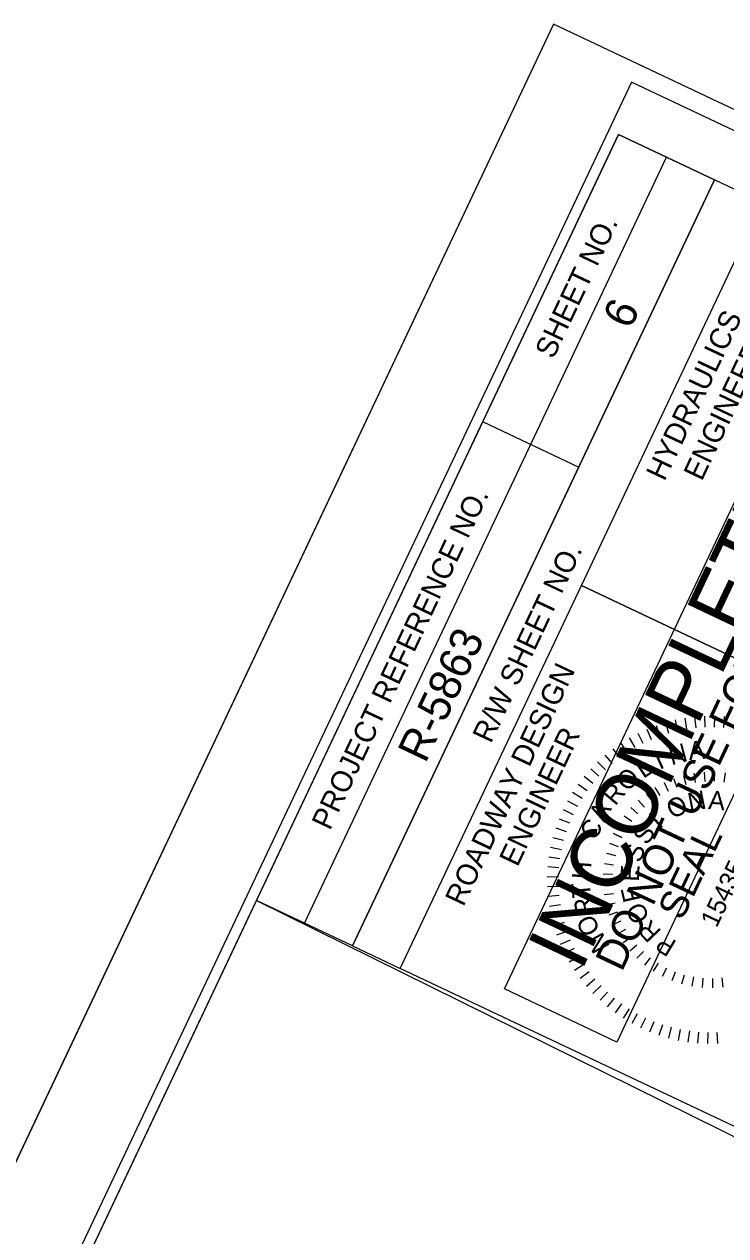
# Model space of a CAD drawing. Extents: x 555566 to 557881, y 503985 to 506091.
# Drawn here: x 556761.6 to 556927.2, y 505805.2 to 506091.2 of the extents above; entities that cross this region are included whole.
import ezdxf

# ---------------------------------------------------------------- set-up
doc = ezdxf.new("R2010")
doc.units = 0
for name, color, linetype in [('Old_Level_21', 7, 'Continuous'), ('Sheet Border Standard 30in CELL', 7, 'Continuous'), ('Sheet Clip Boundary CELL', 7, 'Continuous'), ('Sheet Cutting Line CELL', 7, 'Continuous'), ('Sheet Data Field CELL', 7, 'Continuous'), ('Sheet Plot Border Inside CELL', 7, 'Continuous'), ('Sheet Plot Border Outside CELL', 7, 'Continuous'), ('Sheet Sticker Incomplete CELL', 7, 'Continuous')]:
    doc.layers.add(name, color=color, linetype=linetype)

msp = doc.modelspace()

# ---------------------------------------------------------------- linework, layer by layer
at = {"layer": 'Old_Level_21'}
for p, q in [((556910.79, 505925.66), (556911.68, 505923.17)), ((556913.01, 505926.37), (556913.75, 505923.84)), ((556915.28, 505926.96), (556915.86, 505924.39)), ((556917.57, 505927.4), (556918, 505924.8)), ((556919.89, 505927.71), (556920.16, 505925.08)), ((556922.22, 505927.87), (556922.33, 505925.24)), ((556924.56, 505927.89), (556924.5, 505925.26)), ((556926.89, 505927.78), (556926.68, 505925.15)), ((556904.44, 505922.72), (556905.75, 505920.44)), ((556906.49, 505923.82), (556907.67, 505921.47)), ((556908.62, 505924.81), (556909.65, 505922.38)), ((556900.54, 505920.14), (556902.12, 505918.03)), ((556902.45, 505921.49), (556903.9, 505919.29)), ((556896.98, 505917.12), (556898.81, 505915.21)), ((556898.72, 505918.68), (556900.42, 505916.68)), ((556893.81, 505913.68), (556895.86, 505912.02)), ((556895.35, 505915.45), (556897.29, 505913.66)), ((556917.28, 505913.87), (556917.84, 505911.75)), ((556919.69, 505914.39), (556920.04, 505912.22)), ((556922.13, 505914.66), (556922.28, 505912.47)), ((556924.6, 505914.7), (556924.53, 505912.51)), ((556927.06, 505914.5), (556926.77, 505912.32)), ((556892.39, 505911.83), (556894.53, 505910.29)), ((556910.5, 505910.99), (556911.65, 505909.11)), ((556912.66, 505912.17), (556913.62, 505910.19)), ((556914.93, 505913.13), (556915.69, 505911.07)), ((556891.09, 505909.89), (556893.31, 505908.48)), ((556906.57, 505908.03), (556908.05, 505906.41)), ((556908.46, 505909.6), (556909.78, 505907.85)), ((556888.83, 505905.8), (556891.21, 505904.67)), ((556889.9, 505907.88), (556892.21, 505906.61)), ((556904.83, 505906.28), (556906.47, 505904.81)), ((556887.89, 505903.66), (556890.34, 505902.67)), ((556901.91, 505902.32), (556903.79, 505901.19)), ((556903.27, 505904.37), (556905.04, 505903.06)), ((556887.09, 505901.46), (556889.59, 505900.63)), ((556900.75, 505900.15), (556902.73, 505899.21)), ((556902.73, 505899.21), (556900.75, 505900.15)), ((556885.88, 505896.96), (556888.46, 505896.42)), ((556886.41, 505899.23), (556888.96, 505898.55)), ((556899.8, 505897.87), (556901.87, 505897.13)), ((556885.48, 505894.65), (556888.09, 505894.28)), ((556899.08, 505895.52), (556901.21, 505894.97)), ((556885.22, 505892.33), (556887.85, 505892.12)), ((556898.58, 505893.11), (556900.76, 505892.77)), ((556885.11, 505890), (556887.74, 505889.94)), ((556898.31, 505888.19), (556900.5, 505888.28)), ((556898.33, 505890.65), (556900.52, 505890.53)), ((556885.13, 505887.66), (556887.77, 505887.76)), ((556885.29, 505885.33), (556887.92, 505885.59)), ((556898.52, 505885.74), (556900.7, 505886.03)), ((556885.6, 505883.01), (556888.2, 505883.43)), ((556898.98, 505883.31), (556901.12, 505883.82)), ((556886.05, 505880.72), (556888.62, 505881.3)), ((556899.67, 505880.95), (556901.75, 505881.66)), ((556900.58, 505878.66), (556902.58, 505879.57)), ((556886.63, 505878.45), (556889.16, 505879.19)), ((556887.35, 505876.23), (556889.83, 505877.12)), ((556901.7, 505876.47), (556903.61, 505877.57)), ((556888.2, 505874.06), (556890.62, 505875.09)), ((556903.04, 505874.4), (556904.83, 505875.67)), ((556904.56, 505872.46), (556906.22, 505873.91)), ((556889.18, 505871.93), (556891.53, 505873.11)), ((556890.28, 505869.88), (556892.57, 505871.19)), ((556906.27, 505870.69), (556907.78, 505872.29)), ((556908.14, 505869.09), (556909.49, 505870.82)), ((556891.51, 505867.89), (556893.71, 505869.34)), ((556910.16, 505867.67), (556911.33, 505869.53)), ((556912.3, 505866.46), (556913.29, 505868.42)), ((556892.86, 505865.98), (556894.97, 505867.56)), ((556894.32, 505864.15), (556896.33, 505865.86)), ((556914.55, 505865.45), (556915.35, 505867.5)), ((556916.89, 505864.68), (556917.48, 505866.79)), ((556919.29, 505864.12), (556919.68, 505866.28)), ((556921.74, 505863.81), (556921.91, 505866)), ((556924.2, 505863.73), (556924.16, 505865.93)), ((556926.65, 505863.89), (556926.41, 505866.07)), ((556895.89, 505862.42), (556897.79, 505864.25)), ((556897.55, 505860.78), (556899.34, 505862.73)), ((556899.32, 505859.25), (556900.98, 505861.3)), ((556901.17, 505857.83), (556902.71, 505859.97)), ((556903.11, 505856.53), (556904.52, 505858.75)), ((556905.12, 505855.34), (556906.39, 505857.65)), ((556907.2, 505854.27), (556908.33, 505856.65)), ((556909.34, 505853.33), (556910.33, 505855.78)), ((556911.54, 505852.53), (556912.37, 505855.03)), ((556913.77, 505851.85), (556914.46, 505854.4)), ((556916.05, 505851.32), (556916.58, 505853.9)), ((556918.35, 505850.92), (556918.72, 505853.53)), ((556920.67, 505850.66), (556920.88, 505853.29)), ((556923.01, 505850.55), (556923.06, 505853.18)), ((556925.34, 505850.57), (556925.24, 505853.2))]:
    msp.add_line(p, q, dxfattribs=at)
at = {"layer": 'Sheet Border Standard 30in CELL'}
for p, q in [((556827.79, 505878.96), (556913.28, 506059.82)), ((556839.1, 505873.62), (556924.58, 506054.48)), ((556839.1, 505873.62), (556924.58, 506054.48)), ((556869.93, 505997.36), (556892.53, 505986.68)), ((556893.15, 505958.73), (556994.82, 505910.68)), ((556839.1, 505873.62), (556850.4, 505868.28))]:
    msp.add_line(p, q, dxfattribs=at)
for points in [[(556901.93, 506065.19), (556260.95, 504709.04), (557210.25, 504260.35), (557851.24, 505616.5)], [(556816.45, 505884.32), (556901.93, 506065.19), (556924.58, 506054.48), (556839.1, 505873.62)], [(556893.15, 505958.73), (556935.88, 506049.14), (557037.59, 506001.07), (556994.86, 505910.66)], [(556850.4, 505868.28), (556893.15, 505958.73), (556994.86, 505910.66), (556952.11, 505820.2)]]:
    msp.add_lwpolyline(points, close=True, dxfattribs=at)
at = {"layer": 'Sheet Clip Boundary CELL'}
msp.add_lwpolyline([(557047.43, 504351.91), (557011.84, 504393.69), (556904.12, 504418.34), (556404.92, 505013.64), (556816.45, 505884.32), (556973.87, 505806.54), (557008.7, 505860.07), (557008.7, 505860.07), (557512.37, 505750.31), (557851.24, 505616.5), (557197.58, 504288.36)], close=True, dxfattribs=at)
at = {"layer": 'Sheet Cutting Line CELL'}
msp.add_line((556886.6, 506091.24), (556166.98, 504568.74), dxfattribs=at)
at = {"layer": 'Sheet Plot Border Inside CELL'}
msp.add_lwpolyline([(556904.97, 506077.58), (556192.83, 504570.9), (557146.75, 504120.03), (557858.88, 505626.71)], close=True, dxfattribs=at)
at = {"layer": 'Sheet Plot Border Outside CELL'}
msp.add_lwpolyline([(556886.6, 506091.24), (556166.98, 504568.74), (557161.49, 504098.68), (557881.1, 505621.18)], close=True, dxfattribs=at)
at = {"layer": 'Sheet Sticker Incomplete CELL'}
msp.add_lwpolyline([(556901.55, 505850.92), (556874.99, 505863.48), (556953.52, 506029.6), (556980.07, 506017.05)], close=True, dxfattribs=at)

# ---------------------------------------------------------------- texts
at = {"layer": 'Old_Level_21'}
for s, height, rotation, p in [('I', 4.39, 24.2013, (556911.6, 505915.14)), ('N', 4.39, 14.9069, (556914.42, 505916.24)), ('A', 4.39, 5.1394, (556918.59, 505917.47)), ('L', 4.39, 33.7768, (556907.78, 505913.03)), ('O', 4.39, 46.9131, (556904.1, 505909.84)), ('R', 4.39, 49.9699, (556901.14, 505906.53)), ('O', 4.39, 26.3816, (556914.61, 505903.5)), ('N', 4.39, 11.0854, (556918.72, 505905.3)), ('A', 4.39, 355.7892, (556923, 505905.93)), ('A', 4.39, 61.9792, (556898.56, 505902.61)), ('I', 4.39, 41.6779, (556911.55, 505901.03)), ('C', 4.39, 61.9792, (556896.42, 505898.31)), ('S', 4.39, 56.9741, (556908.69, 505897.22)), ('SEAL', 6.591, 64.6223, (556916.93, 505879.4)), ('S', 4.39, 72.2704, (556907.14, 505893.1)), ('15435', 4.391, 64.6223, (556925.08, 505877.72)), ('H', 4.39, 85.6899, (556895.23, 505889.21)), ('E', 4.39, 87.5666, (556906.74, 505888.73)), ('T', 4.39, 95.1219, (556895.44, 505885.19)), ('R', 4.39, 103.2828, (556896.39, 505881.47)), ('F', 4.39, 102.8629, (556907.48, 505884.49)), ('O', 4.39, 118.1591, (556909.43, 505880.34)), ('O', 4.39, 116.3396, (556897.7, 505877.33)), ('R', 4.39, 133.4554, (556912.24, 505877.08)), ('N', 4.39, 118.299, (556899.97, 505873.46)), ('P', 4.39, 148.7516, (556915.89, 505874.61))]:
    msp.add_text(s, height=height, rotation=rotation, dxfattribs=at).set_placement(p)
at = {"layer": 'Sheet Border Standard 30in CELL'}
for s, height, p in [('SHEET NO.', 5, (556886.52, 506011.97)), ('HYDRAULICS', 5, (556912.76, 505983.14)), ('ENGINEER', 5, (556921.57, 505983.18)), ('PROJECT REFERENCE NO.', 5.0001, (556833.8, 505900.68)), ('R/W SHEET NO.', 5.0001, (556871.77, 505921.22)), ('ROADWAY DESIGN', 5.0001, (556865.29, 505882.7)), ('ENGINEER', 5, (556878.07, 505892.08))]:
    msp.add_text(s, height=height, rotation=64.7021, dxfattribs=at).set_placement(p)
at = {"layer": 'Sheet Data Field CELL'}
for s, p in [('6', (556904.69, 506018.95)), ('R-5863', (556856.33, 505916.52))]:
    msp.add_text(s, height=7.5, rotation=64.7021, dxfattribs=at).set_placement(p)
at = {"layer": 'Sheet Sticker Incomplete CELL'}
for s, height, p in [('INCOMPLETE PLANS', 14.4, (556893.1, 505867.31)), ('DO NOT USE FOR R/W ACQUISITION', 7.2, (556902.69, 505867.27))]:
    msp.add_text(s, height=height, rotation=64.7021, dxfattribs=at).set_placement(p)

doc.saveas('drawing.dxf')
